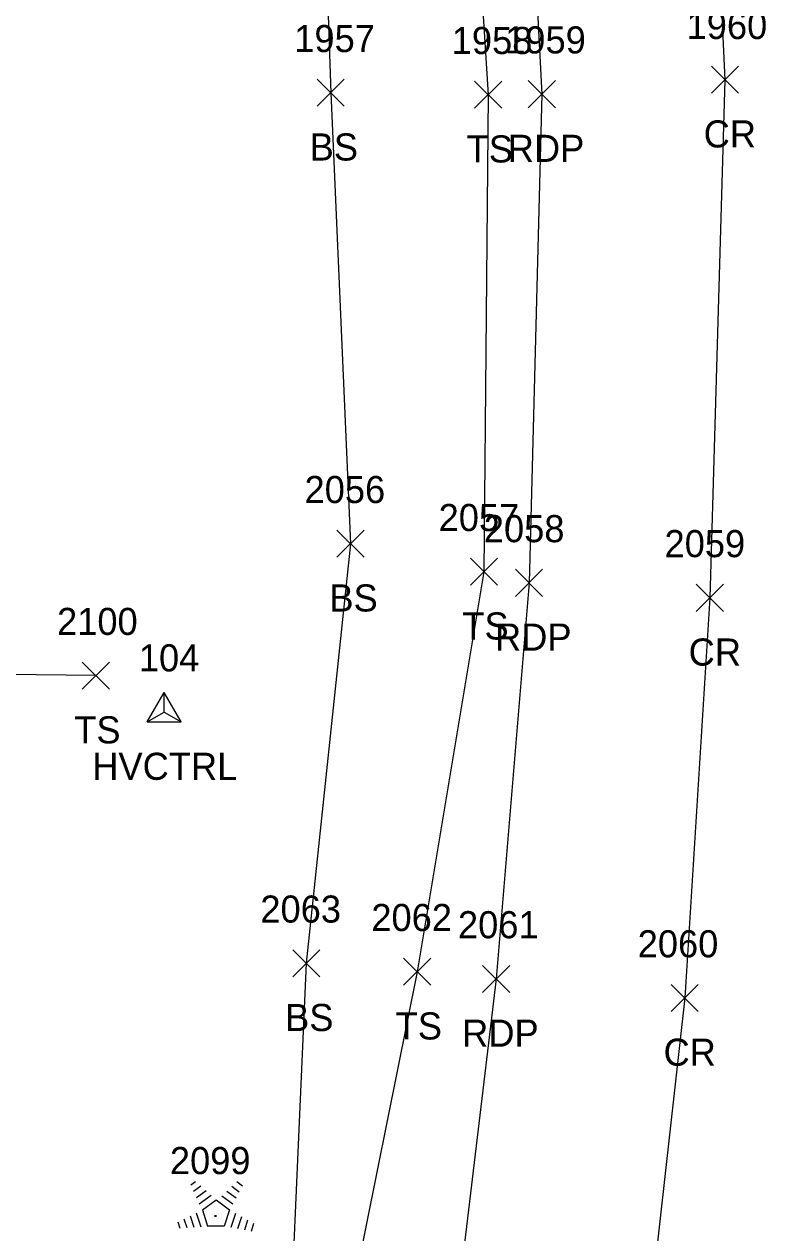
# Model space of a CAD drawing. Extents: x 1651305 to 1654558, y 539481 to 548441.
# Drawn here: x 1654335.1 to 1654389.8, y 544348.7 to 544437.8 of the extents above; entities that cross this region are included whole.
import ezdxf

# ---------------------------------------------------------------- set-up
doc = ezdxf.new("R2010")
doc.units = 0
for name, color, linetype in [('C_A', 7, 'Continuous'), ('C_I', 7, 'Continuous'), ('CPSM', 7, 'Continuous'), ('L_A', 7, 'Continuous'), ('L_I', 7, 'Continuous'), ('L_TIC', 7, 'Continuous'), ('LELB', 7, 'Continuous'), ('LTC', 7, 'Continuous'), ('P_A', 7, 'Continuous'), ('P_I', 7, 'Continuous'), ('P_TIC', 7, 'Continuous'), ('PET', 7, 'Continuous'), ('PRC', 7, 'Continuous')]:
    doc.layers.add(name, color=color, linetype=linetype)

msp = doc.modelspace()

# ---------------------------------------------------------------- linework, layer by layer
at = {"layer": 'CPSM'}
for p, q in [((1654344.21, 544386.372), (1654345.46, 544388.537)), ((1654346.71, 544386.372), (1654345.46, 544388.537)), ((1654345.46, 544387.093), (1654345.46, 544388.537)), ((1654344.21, 544386.372), (1654345.46, 544387.093)), ((1654345.46, 544387.093), (1654345.46, 544387.093)), ((1654345.46, 544387.093), (1654346.71, 544386.372)), ((1654344.21, 544386.372), (1654346.71, 544386.372))]:
    msp.add_line(p, q, dxfattribs=at)
at = {"layer": 'L_TIC'}
for points in [[(1654356.746, 544431.787), (1654358.746, 544433.787)], [(1654358.746, 544431.787), (1654356.746, 544433.787)], [(1654368.361, 544431.643), (1654370.361, 544433.643)], [(1654370.361, 544431.643), (1654368.361, 544433.643)], [(1654358.203, 544398.513), (1654360.203, 544400.513)], [(1654360.203, 544398.513), (1654358.203, 544400.513)], [(1654368.042, 544396.447), (1654370.042, 544398.447)], [(1654370.042, 544396.447), (1654368.042, 544398.447)], [(1654339.413, 544388.781), (1654341.413, 544390.781)], [(1654341.413, 544388.781), (1654339.413, 544390.781)], [(1654354.938, 544367.559), (1654356.938, 544369.559)], [(1654356.938, 544367.559), (1654354.938, 544369.559)], [(1654363.123, 544366.936), (1654365.123, 544368.936)], [(1654365.123, 544366.936), (1654363.123, 544368.936)]]:
    msp.add_lwpolyline(points, dxfattribs=at)
at = {"layer": 'LELB'}
for points in [[(1654343.576, 544585.046), (1654350.339, 544565.292), (1654357.012, 544542.017), (1654364.115, 544503.195), (1654366.803, 544473.036), (1654369.361, 544432.643), (1654369.042, 544397.447), (1654364.123, 544367.936), (1654358.932, 544342.149)], [(1654331.964, 544545.967), (1654352.544, 544530.798), (1654354.982, 544503.342), (1654356.395, 544472.139), (1654357.746, 544432.787), (1654359.203, 544399.513), (1654355.938, 544368.559), (1654354.81, 544342.889)], [(1654340.413, 544389.781), (1654309.6, 544390.142), (1654259.862, 544399.585)]]:
    msp.add_lwpolyline(points, dxfattribs=at)
at = {"layer": 'LTC'}
for p, q in [((1654347.42, 544352.211), (1654347.774, 544352.469)), ((1654347.629, 544351.746), (1654348.158, 544352.13)), ((1654350.447, 544352.104), (1654350.996, 544351.704)), ((1654350.818, 544352.452), (1654351.237, 544352.147)), ((1654347.839, 544351.28), (1654348.543, 544351.791)), ((1654348.048, 544350.814), (1654348.927, 544351.452)), ((1654349.705, 544351.407), (1654350.514, 544350.818)), ((1654350.076, 544351.755), (1654350.755, 544351.261)), ((1654348.273, 544350.359), (1654349.285, 544351.094)), ((1654348.273, 544350.359), (1654348.66, 544349.166)), ((1654349.285, 544351.094), (1654350.282, 544350.369)), ((1654350.282, 544350.369), (1654349.891, 544349.166)), ((1654346.452, 544349.491), (1654346.604, 544349.023)), ((1654346.908, 544349.707), (1654347.119, 544349.056)), ((1654347.363, 544349.924), (1654347.634, 544349.089)), ((1654347.818, 544350.14), (1654348.149, 544349.121)), ((1654350.719, 544350.098), (1654350.381, 544349.059)), ((1654351.164, 544349.848), (1654350.876, 544348.963)), ((1654351.608, 544349.598), (1654351.371, 544348.868)), ((1654349.891, 544349.166), (1654348.66, 544349.166)), ((1654352.053, 544349.347), (1654351.866, 544348.773))]:
    msp.add_line(p, q, dxfattribs=at)
at = {"layer": 'P_TIC'}
for points in [[(1654385.821, 544432.75), (1654387.821, 544434.75)], [(1654387.821, 544432.75), (1654385.821, 544434.75)], [(1654372.313, 544431.687), (1654374.313, 544433.687)], [(1654374.313, 544431.687), (1654372.313, 544433.687)], [(1654371.374, 544395.626), (1654373.374, 544397.626)], [(1654373.374, 544395.626), (1654371.374, 544397.626)], [(1654384.713, 544394.522), (1654386.713, 544396.522)], [(1654386.713, 544394.522), (1654384.713, 544396.522)], [(1654368.948, 544366.404), (1654370.948, 544368.404)], [(1654370.948, 544366.404), (1654368.948, 544368.404)], [(1654382.86, 544364.997), (1654384.86, 544366.997)], [(1654384.86, 544364.997), (1654382.86, 544366.997)]]:
    msp.add_lwpolyline(points, dxfattribs=at)
at = {"layer": 'PET'}
msp.add_lwpolyline([(1654345.042, 544588.36), (1654352.836, 544566.031), (1654357.709, 544551.643), (1654360.669, 544540.213), (1654367.97, 544503.911), (1654371.191, 544473.217), (1654373.313, 544432.687), (1654372.374, 544396.626), (1654369.948, 544367.404), (1654366.855, 544341.544), (1654364.487, 544322.02), (1654359.176, 544276.501), (1654356.39, 544249.38), (1654353.626, 544216.56), (1654349.272, 544178.191), (1654347.294, 544164.707), (1654345.692, 544149.484), (1654340.924, 544117.477), (1654336.045, 544077.134)], dxfattribs=at)
at = {"layer": 'PRC'}
msp.add_lwpolyline([(1654350.59, 544607.191), (1654355.931, 544592.699), (1654363.685, 544570.628), (1654372.223, 544542.272), (1654380.244, 544505.389), (1654384.95, 544473.916), (1654386.821, 544433.75), (1654385.713, 544395.522), (1654383.86, 544365.997), (1654380.919, 544339.646), (1654377.996, 544311.086), (1654373.889, 544274.842), (1654369.008, 544231.012), (1654366.63, 544212.463), (1654362.444, 544177.974), (1654359.488, 544151.886), (1654354.071, 544107.932), (1654348.42, 544063.008)], dxfattribs=at)

# ---------------------------------------------------------------- texts
at = {"layer": 'C_A'}
msp.add_text('HVCTRL', height=2, dxfattribs=at).set_placement((1654340.153, 544382.093))
at = {"layer": 'C_I'}
msp.add_text('104', height=2, dxfattribs=at).set_placement((1654343.586, 544390.093))
at = {"layer": 'L_A'}
for s, p in [('BS', (1654356.187, 544427.787)), ('TS', (1654367.77, 544427.643)), ('BS', (1654357.644, 544394.513)), ('TS', (1654367.451, 544392.447)), ('TS', (1654338.822, 544384.781)), ('BS', (1654354.379, 544363.559)), ('TS', (1654362.533, 544362.936))]:
    msp.add_text(s, height=2, dxfattribs=at).set_placement(p)
at = {"layer": 'L_I'}
for s, p in [('1957', (1654355.053, 544435.787)), ('1958', (1654366.668, 544435.643)), ('2056', (1654355.81, 544402.513)), ('2057', (1654365.703, 544400.447)), ('2100', (1654337.554, 544392.781)), ('2063', (1654352.552, 544371.559)), ('2062', (1654360.738, 544370.936)), ('2099', (1654345.878, 544353.003))]:
    msp.add_text(s, height=2, dxfattribs=at).set_placement(p)
at = {"layer": 'LTC'}
msp.add_text('.', height=1.037, rotation=270, dxfattribs=at).set_placement((1654349.167, 544350.107))
at = {"layer": 'P_A'}
for s, p in [('CR', (1654385.254, 544428.75)), ('RDP', (1654370.801, 544427.687)), ('RDP', (1654369.862, 544391.626)), ('CR', (1654384.146, 544390.522)), ('RDP', (1654367.436, 544362.404)), ('CR', (1654382.293, 544360.997))]:
    msp.add_text(s, height=2, dxfattribs=at).set_placement(p)
at = {"layer": 'P_I'}
for s, p in [('1960', (1654383.994, 544436.75)), ('1959', (1654370.612, 544435.687)), ('2058', (1654369.035, 544399.626)), ('2059', (1654382.367, 544398.522)), ('2061', (1654367.129, 544370.404)), ('2060', (1654380.387, 544368.997))]:
    msp.add_text(s, height=2, dxfattribs=at).set_placement(p)

doc.saveas('drawing.dxf')
